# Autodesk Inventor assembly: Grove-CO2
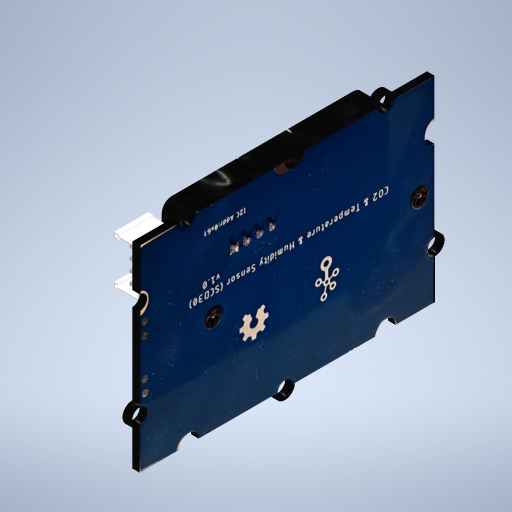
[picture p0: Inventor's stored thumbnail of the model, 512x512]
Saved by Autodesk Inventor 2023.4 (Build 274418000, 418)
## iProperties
Created: 2025-02
Part Number: Grove-CO2
Document SubType Name: Assembly
Designer: bruno
Author: bruno
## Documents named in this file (4)
- C:\Users\bruno\Documents\1-Cours-2024-25\1STI2D\IT\Escape-game\Inventor_uhl\Boite\Grove-CO2\Grove-CO2.iam
- C:\Users\bruno\Documents\1-Cours-2024-25\1STI2D\IT\Escape-game\Inventor_uhl\Boite\Grove-CO2\CO2-Sensor.ipt
- C:\Users\bruno\Documents\1-Cours-2024-25\1STI2D\IT\Escape-game\Inventor_uhl\Boite\Grove-CO2\boitier.ipt
- C:\Users\bruno\Documents\1-Cours-2024-25\1STI2D\IT\Escape-game\Inventor_uhl\Boite\Grove-CO2\connecteur.ipt
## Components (3 placed, 3 different names)
1. CO2-Sensor:1 — Placage:1, Placage:2, Affleurement:1, Affleurement:2, Tangente:1
2. boitier:1 — Placage:1, Affleurement:2, Tangente:1
3. connecteur:1 — Placage:2, Affleurement:1
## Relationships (5: Mate 2, Flush 2, Tangent 1)
- Placage:1 [Mate]: CO2-Sensor:1 ↔ boitier:1
- Placage:2 [Mate]: CO2-Sensor:1 ↔ connecteur:1
- Affleurement:1 [Flush]: CO2-Sensor:1 ↔ connecteur:1
- Affleurement:2 [Flush]: CO2-Sensor:1 ↔ boitier:1
- Tangente:1: CO2-Sensor:1 ↔ boitier:1
